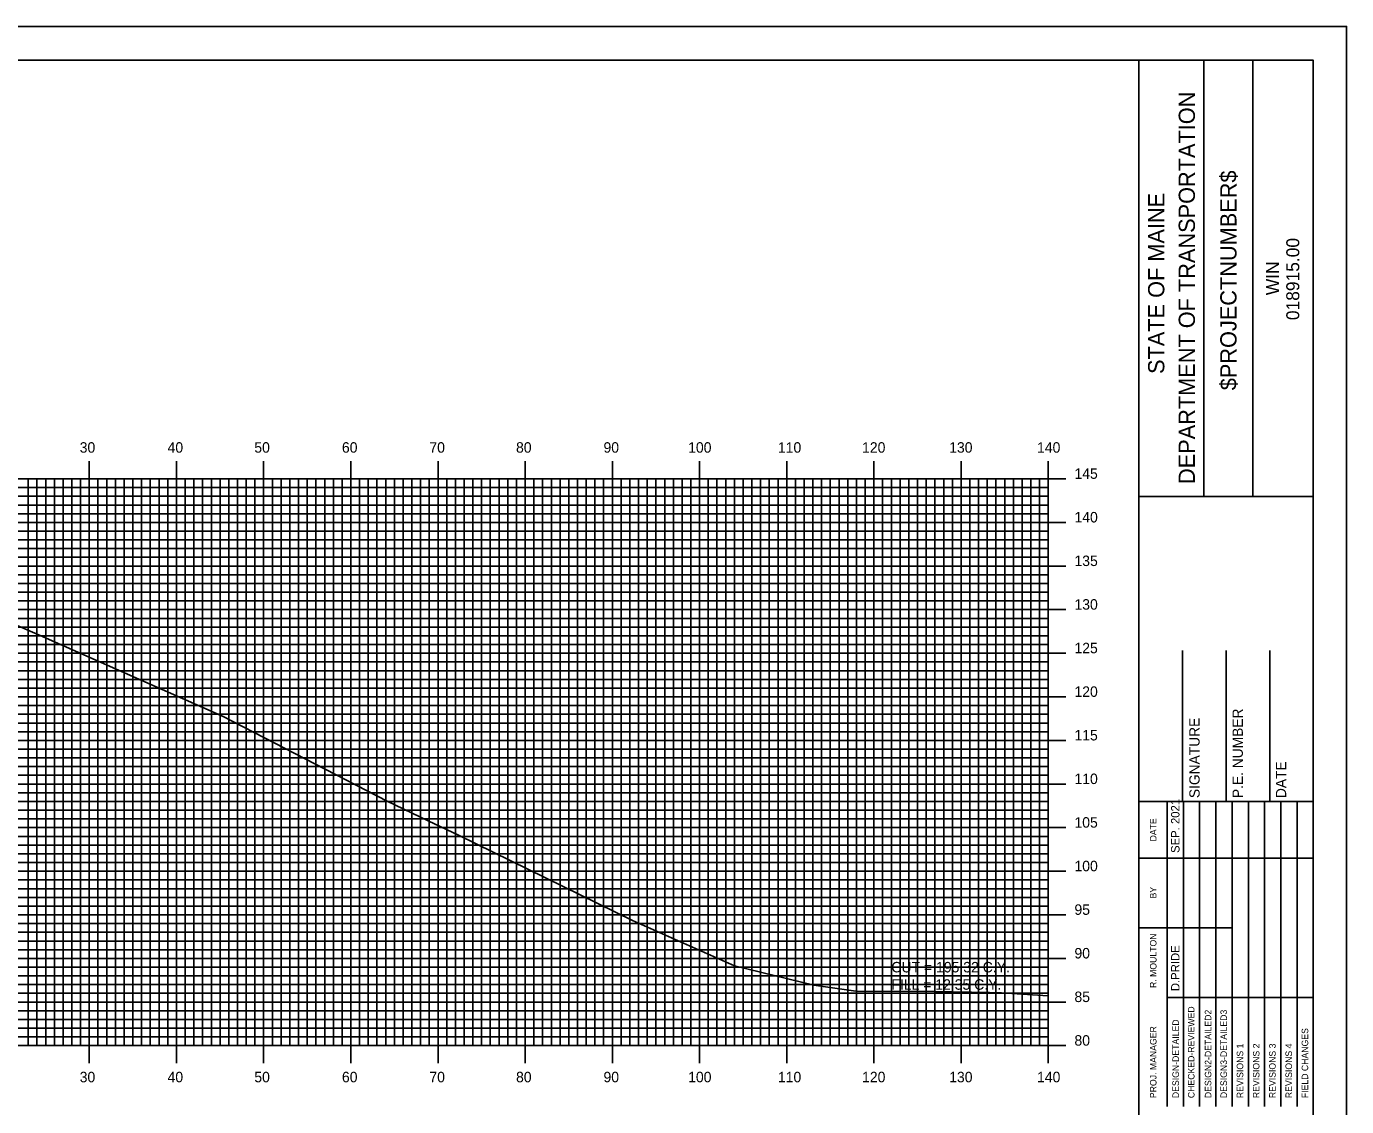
# Model space of a CAD drawing. Extents: x 859471 to 859814, y 364765 to 364985.
# Drawn here: x 859659.7 to 859811.1, y 364861.3 to 364985.2 of the extents above; entities that cross this region are included whole.
import ezdxf

# ---------------------------------------------------------------- set-up
doc = ezdxf.new("R2010")
doc.units = 0
for name, color, linetype in [('BORDER', 7, 'Continuous'), ('D_Text_Standard', 7, 'Continuous'), ('H_V ANNOTATION', 7, 'Continuous'), ('MAJOR', 7, 'Continuous'), ('MINOR', 7, 'Continuous'), ('PLOT BOUNDARY', 7, 'Continuous'), ('S_Roadway_Centerline', 7, 'Continuous')]:
    doc.layers.add(name, color=color, linetype=linetype)

msp = doc.modelspace()

# ---------------------------------------------------------------- linework, layer by layer
at = {"layer": 'BORDER'}
for p, q in [((859787.27, 364771.3), (859787.27, 364981.3)), ((859794.73, 364931.3), (859794.73, 364981.3)), ((859800.32, 364931.3), (859800.32, 364981.3)), ((859787.27, 364931.29), (859807.27, 364931.29)), ((859792.27, 364896.31), (859792.27, 364913.6)), ((859797.27, 364896.31), (859797.27, 364913.6)), ((859802.27, 364896.31), (859802.27, 364913.6)), ((859787.27, 364896.31), (859807.27, 364896.31))]:
    msp.add_line(p, q, dxfattribs=at)
msp.add_lwpolyline([(859487.27, 364771.3), (859807.27, 364771.3), (859807.27, 364981.3), (859487.27, 364981.3)], close=True, dxfattribs=at)
for points in [[(859790.5, 364889.81), (859790.5, 364896.31)], [(859792.37, 364861.31), (859792.37, 364896.31)], [(859794.23, 364896.31), (859794.23, 364861.31)], [(859796.09, 364861.31), (859796.09, 364896.31)], [(859797.96, 364861.31), (859797.96, 364896.31)], [(859799.82, 364861.31), (859799.82, 364896.31)], [(859801.68, 364861.31), (859801.68, 364896.31)], [(859803.55, 364861.31), (859803.55, 364896.31)], [(859805.41, 364861.31), (859805.41, 364896.31)], [(859790.5, 364861.31), (859790.5, 364894.9)], [(859787.27, 364889.81), (859807.27, 364889.81)], [(859787.27, 364881.81), (859790.5, 364881.81)], [(859790.5, 364881.81), (859797.96, 364881.81)], [(859790.5, 364873.81), (859807.27, 364873.81)]]:
    msp.add_lwpolyline(points, dxfattribs=at)
at = {"layer": 'MAJOR'}
for p, q in [((859666.87, 364935.31), (859666.87, 364933.3)), ((859676.87, 364935.31), (859676.87, 364933.3)), ((859686.87, 364935.31), (859686.87, 364933.3)), ((859696.87, 364935.31), (859696.87, 364933.3)), ((859706.87, 364935.31), (859706.87, 364933.3)), ((859716.87, 364935.31), (859716.87, 364933.3)), ((859726.87, 364935.31), (859726.87, 364933.3)), ((859736.87, 364935.31), (859736.87, 364933.3)), ((859746.87, 364935.31), (859746.87, 364933.3)), ((859756.87, 364935.31), (859756.87, 364933.3)), ((859766.87, 364935.31), (859766.87, 364933.3)), ((859776.87, 364935.31), (859776.87, 364933.3)), ((859496.87, 364933.3), (859776.87, 364933.3)), ((859496.87, 364933.3), (859776.87, 364933.3)), ((859666.87, 364868.3), (859666.87, 364933.3)), ((859676.87, 364868.3), (859676.87, 364933.3)), ((859686.87, 364868.3), (859686.87, 364933.3)), ((859696.87, 364868.3), (859696.87, 364933.3)), ((859706.87, 364868.3), (859706.87, 364933.3)), ((859716.87, 364868.3), (859716.87, 364933.3)), ((859726.87, 364868.3), (859726.87, 364933.3)), ((859736.87, 364868.3), (859736.87, 364933.3)), ((859746.87, 364868.3), (859746.87, 364933.3)), ((859756.87, 364868.3), (859756.87, 364933.3)), ((859766.87, 364868.3), (859766.87, 364933.3)), ((859778.88, 364933.3), (859774.87, 364933.3)), ((859776.87, 364868.3), (859776.87, 364933.3)), ((859776.87, 364868.3), (859776.87, 364933.3)), ((859496.87, 364928.3), (859776.87, 364928.3)), ((859778.88, 364928.3), (859774.87, 364928.3)), ((859496.87, 364923.3), (859776.87, 364923.3)), ((859778.88, 364923.3), (859774.87, 364923.3)), ((859496.87, 364918.3), (859776.87, 364918.3)), ((859778.88, 364918.3), (859774.87, 364918.3)), ((859496.87, 364913.3), (859776.87, 364913.3)), ((859778.88, 364913.3), (859774.87, 364913.3)), ((859496.87, 364908.3), (859776.87, 364908.3)), ((859778.88, 364908.3), (859774.87, 364908.3)), ((859496.87, 364903.3), (859776.87, 364903.3)), ((859778.88, 364903.3), (859774.87, 364903.3)), ((859496.87, 364898.3), (859776.87, 364898.3)), ((859778.88, 364898.3), (859774.87, 364898.3)), ((859496.87, 364893.3), (859776.87, 364893.3)), ((859778.88, 364893.3), (859774.87, 364893.3)), ((859496.87, 364888.3), (859776.87, 364888.3)), ((859778.88, 364888.3), (859774.87, 364888.3)), ((859496.87, 364883.3), (859776.87, 364883.3)), ((859778.88, 364883.3), (859774.87, 364883.3)), ((859496.87, 364878.3), (859776.87, 364878.3)), ((859778.88, 364878.3), (859774.87, 364878.3)), ((859496.87, 364873.3), (859776.87, 364873.3)), ((859778.88, 364873.3), (859774.87, 364873.3)), ((859496.87, 364868.3), (859776.87, 364868.3)), ((859496.87, 364868.3), (859776.87, 364868.3)), ((859666.87, 364866.3), (859666.87, 364868.3)), ((859676.87, 364866.3), (859676.87, 364868.3)), ((859686.87, 364866.3), (859686.87, 364868.3)), ((859696.87, 364866.3), (859696.87, 364868.3)), ((859706.87, 364866.3), (859706.87, 364868.3)), ((859716.87, 364866.3), (859716.87, 364868.3)), ((859726.87, 364866.3), (859726.87, 364868.3)), ((859736.87, 364866.3), (859736.87, 364868.3)), ((859746.87, 364866.3), (859746.87, 364868.3)), ((859756.87, 364866.3), (859756.87, 364868.3)), ((859766.87, 364866.3), (859766.87, 364868.3)), ((859778.88, 364868.3), (859774.87, 364868.3)), ((859776.87, 364866.3), (859776.87, 364868.3))]:
    msp.add_line(p, q, dxfattribs=at)
at = {"layer": 'MINOR'}
for p, q in [((859659.87, 364868.3), (859659.87, 364933.3)), ((859660.87, 364868.3), (859660.87, 364933.3)), ((859661.87, 364868.3), (859661.87, 364933.3)), ((859662.87, 364868.3), (859662.87, 364933.3)), ((859663.87, 364868.3), (859663.87, 364933.3)), ((859664.87, 364868.3), (859664.87, 364933.3)), ((859665.87, 364868.3), (859665.87, 364933.3)), ((859667.87, 364868.3), (859667.87, 364933.3)), ((859668.87, 364868.3), (859668.87, 364933.3)), ((859669.87, 364868.3), (859669.87, 364933.3)), ((859670.87, 364868.3), (859670.87, 364933.3)), ((859671.87, 364868.3), (859671.87, 364933.3)), ((859672.87, 364868.3), (859672.87, 364933.3)), ((859673.87, 364868.3), (859673.87, 364933.3)), ((859674.87, 364868.3), (859674.87, 364933.3)), ((859675.87, 364868.3), (859675.87, 364933.3)), ((859677.87, 364868.3), (859677.87, 364933.3)), ((859678.87, 364868.3), (859678.87, 364933.3)), ((859679.87, 364868.3), (859679.87, 364933.3)), ((859680.87, 364868.3), (859680.87, 364933.3)), ((859681.87, 364868.3), (859681.87, 364933.3)), ((859682.87, 364868.3), (859682.87, 364933.3)), ((859683.87, 364868.3), (859683.87, 364933.3)), ((859684.87, 364868.3), (859684.87, 364933.3)), ((859685.87, 364868.3), (859685.87, 364933.3)), ((859687.87, 364868.3), (859687.87, 364933.3)), ((859688.87, 364868.3), (859688.87, 364933.3)), ((859689.87, 364868.3), (859689.87, 364933.3)), ((859690.87, 364868.3), (859690.87, 364933.3)), ((859691.87, 364868.3), (859691.87, 364933.3)), ((859692.87, 364868.3), (859692.87, 364933.3)), ((859693.87, 364868.3), (859693.87, 364933.3)), ((859694.87, 364868.3), (859694.87, 364933.3)), ((859695.87, 364868.3), (859695.87, 364933.3)), ((859697.87, 364868.3), (859697.87, 364933.3)), ((859698.87, 364868.3), (859698.87, 364933.3)), ((859699.87, 364868.3), (859699.87, 364933.3)), ((859700.87, 364868.3), (859700.87, 364933.3)), ((859701.87, 364868.3), (859701.87, 364933.3)), ((859702.87, 364868.3), (859702.87, 364933.3)), ((859703.87, 364868.3), (859703.87, 364933.3)), ((859704.87, 364868.3), (859704.87, 364933.3)), ((859705.87, 364868.3), (859705.87, 364933.3)), ((859707.87, 364868.3), (859707.87, 364933.3)), ((859708.87, 364868.3), (859708.87, 364933.3)), ((859709.87, 364868.3), (859709.87, 364933.3)), ((859710.87, 364868.3), (859710.87, 364933.3)), ((859711.87, 364868.3), (859711.87, 364933.3)), ((859712.87, 364868.3), (859712.87, 364933.3)), ((859713.87, 364868.3), (859713.87, 364933.3)), ((859714.87, 364868.3), (859714.87, 364933.3)), ((859715.87, 364868.3), (859715.87, 364933.3)), ((859717.87, 364868.3), (859717.87, 364933.3)), ((859718.87, 364868.3), (859718.87, 364933.3)), ((859719.87, 364868.3), (859719.87, 364933.3)), ((859720.87, 364868.3), (859720.87, 364933.3)), ((859721.87, 364868.3), (859721.87, 364933.3)), ((859722.87, 364868.3), (859722.87, 364933.3)), ((859723.87, 364868.3), (859723.87, 364933.3)), ((859724.87, 364868.3), (859724.87, 364933.3)), ((859725.87, 364868.3), (859725.87, 364933.3)), ((859727.87, 364868.3), (859727.87, 364933.3)), ((859728.87, 364868.3), (859728.87, 364933.3)), ((859729.87, 364868.3), (859729.87, 364933.3)), ((859730.87, 364868.3), (859730.87, 364933.3)), ((859731.87, 364868.3), (859731.87, 364933.3)), ((859732.87, 364868.3), (859732.87, 364933.3)), ((859733.87, 364868.3), (859733.87, 364933.3)), ((859734.87, 364868.3), (859734.87, 364933.3)), ((859735.87, 364868.3), (859735.87, 364933.3)), ((859737.87, 364868.3), (859737.87, 364933.3)), ((859738.87, 364868.3), (859738.87, 364933.3)), ((859739.87, 364868.3), (859739.87, 364933.3)), ((859740.87, 364868.3), (859740.87, 364933.3)), ((859741.87, 364868.3), (859741.87, 364933.3)), ((859742.87, 364868.3), (859742.87, 364933.3)), ((859743.87, 364868.3), (859743.87, 364933.3)), ((859744.87, 364868.3), (859744.87, 364933.3)), ((859745.87, 364868.3), (859745.87, 364933.3)), ((859747.87, 364868.3), (859747.87, 364933.3)), ((859748.87, 364868.3), (859748.87, 364933.3)), ((859749.87, 364868.3), (859749.87, 364933.3)), ((859750.87, 364868.3), (859750.87, 364933.3)), ((859751.87, 364868.3), (859751.87, 364933.3)), ((859752.87, 364868.3), (859752.87, 364933.3)), ((859753.87, 364868.3), (859753.87, 364933.3)), ((859754.87, 364868.3), (859754.87, 364933.3)), ((859755.87, 364868.3), (859755.87, 364933.3)), ((859757.87, 364868.3), (859757.87, 364933.3)), ((859758.87, 364868.3), (859758.87, 364933.3)), ((859759.87, 364868.3), (859759.87, 364933.3)), ((859760.87, 364868.3), (859760.87, 364933.3)), ((859761.87, 364868.3), (859761.87, 364933.3)), ((859762.87, 364868.3), (859762.87, 364933.3)), ((859763.87, 364868.3), (859763.87, 364933.3)), ((859764.87, 364868.3), (859764.87, 364933.3)), ((859765.87, 364868.3), (859765.87, 364933.3)), ((859767.87, 364868.3), (859767.87, 364933.3)), ((859768.87, 364868.3), (859768.87, 364933.3)), ((859769.87, 364868.3), (859769.87, 364933.3)), ((859770.87, 364868.3), (859770.87, 364933.3)), ((859771.87, 364868.3), (859771.87, 364933.3)), ((859772.87, 364868.3), (859772.87, 364933.3)), ((859773.87, 364868.3), (859773.87, 364933.3)), ((859774.87, 364868.3), (859774.87, 364933.3)), ((859775.87, 364868.3), (859775.87, 364933.3)), ((859496.87, 364932.3), (859776.87, 364932.3)), ((859776.87, 364932.3), (859774.87, 364932.3)), ((859496.87, 364931.3), (859776.87, 364931.3)), ((859496.87, 364930.3), (859776.87, 364930.3)), ((859776.87, 364931.3), (859774.87, 364931.3)), ((859776.87, 364930.3), (859774.87, 364930.3)), ((859496.87, 364929.3), (859776.87, 364929.3)), ((859776.87, 364929.3), (859774.87, 364929.3)), ((859496.87, 364927.3), (859776.87, 364927.3)), ((859776.87, 364927.3), (859774.87, 364927.3)), ((859496.87, 364926.3), (859776.87, 364926.3)), ((859776.87, 364926.3), (859774.87, 364926.3)), ((859496.87, 364925.3), (859776.87, 364925.3)), ((859496.87, 364924.3), (859776.87, 364924.3)), ((859776.87, 364925.3), (859774.87, 364925.3)), ((859776.87, 364924.3), (859774.87, 364924.3)), ((859496.87, 364922.3), (859776.87, 364922.3)), ((859776.87, 364922.3), (859774.87, 364922.3)), ((859496.87, 364921.3), (859776.87, 364921.3)), ((859776.87, 364921.3), (859774.87, 364921.3)), ((859496.87, 364920.3), (859776.87, 364920.3)), ((859496.87, 364919.3), (859776.87, 364919.3)), ((859776.87, 364920.3), (859774.87, 364920.3)), ((859776.87, 364919.3), (859774.87, 364919.3)), ((859496.87, 364917.3), (859776.87, 364917.3)), ((859496.87, 364916.3), (859776.87, 364916.3)), ((859776.87, 364917.3), (859774.87, 364917.3)), ((859776.87, 364916.3), (859774.87, 364916.3)), ((859496.87, 364915.3), (859776.87, 364915.3)), ((859776.87, 364915.3), (859774.87, 364915.3)), ((859496.87, 364914.3), (859776.87, 364914.3)), ((859776.87, 364914.3), (859774.87, 364914.3)), ((859496.87, 364912.3), (859776.87, 364912.3)), ((859776.87, 364912.3), (859774.87, 364912.3)), ((859496.87, 364911.3), (859776.87, 364911.3)), ((859496.87, 364910.3), (859776.87, 364910.3)), ((859776.87, 364911.3), (859774.87, 364911.3)), ((859776.87, 364910.3), (859774.87, 364910.3)), ((859496.87, 364909.3), (859776.87, 364909.3)), ((859776.87, 364909.3), (859774.87, 364909.3)), ((859496.87, 364907.3), (859776.87, 364907.3)), ((859776.87, 364907.3), (859774.87, 364907.3)), ((859496.87, 364906.3), (859776.87, 364906.3)), ((859776.87, 364906.3), (859774.87, 364906.3)), ((859496.87, 364905.3), (859776.87, 364905.3)), ((859496.87, 364904.3), (859776.87, 364904.3)), ((859776.87, 364905.3), (859774.87, 364905.3)), ((859776.87, 364904.3), (859774.87, 364904.3)), ((859496.87, 364902.3), (859776.87, 364902.3)), ((859496.87, 364901.3), (859776.87, 364901.3)), ((859776.87, 364902.3), (859774.87, 364902.3)), ((859776.87, 364901.3), (859774.87, 364901.3)), ((859496.87, 364900.3), (859776.87, 364900.3)), ((859776.87, 364900.3), (859774.87, 364900.3)), ((859496.87, 364899.3), (859776.87, 364899.3)), ((859776.87, 364899.3), (859774.87, 364899.3)), ((859496.87, 364897.3), (859776.87, 364897.3)), ((859776.87, 364897.3), (859774.87, 364897.3)), ((859496.87, 364896.3), (859776.87, 364896.3)), ((859496.87, 364895.3), (859776.87, 364895.3)), ((859776.87, 364896.3), (859774.87, 364896.3)), ((859776.87, 364895.3), (859774.87, 364895.3)), ((859496.87, 364894.3), (859776.87, 364894.3)), ((859776.87, 364894.3), (859774.87, 364894.3)), ((859496.87, 364892.3), (859776.87, 364892.3)), ((859776.87, 364892.3), (859774.87, 364892.3)), ((859496.87, 364891.3), (859776.87, 364891.3)), ((859776.87, 364891.3), (859774.87, 364891.3)), ((859496.87, 364890.3), (859776.87, 364890.3)), ((859496.87, 364889.3), (859776.87, 364889.3)), ((859776.87, 364890.3), (859774.87, 364890.3)), ((859776.87, 364889.3), (859774.87, 364889.3)), ((859496.87, 364887.3), (859776.87, 364887.3)), ((859496.87, 364886.3), (859776.87, 364886.3)), ((859776.87, 364887.3), (859774.87, 364887.3)), ((859776.87, 364886.3), (859774.87, 364886.3)), ((859496.87, 364885.3), (859776.87, 364885.3)), ((859776.87, 364885.3), (859774.87, 364885.3)), ((859496.87, 364884.3), (859776.87, 364884.3)), ((859776.87, 364884.3), (859774.87, 364884.3)), ((859496.87, 364882.3), (859776.87, 364882.3)), ((859776.87, 364882.3), (859774.87, 364882.3)), ((859496.87, 364881.3), (859776.87, 364881.3)), ((859496.87, 364880.3), (859776.87, 364880.3)), ((859776.87, 364881.3), (859774.87, 364881.3)), ((859776.87, 364880.3), (859774.87, 364880.3)), ((859496.87, 364879.3), (859776.87, 364879.3)), ((859776.87, 364879.3), (859774.87, 364879.3)), ((859496.87, 364877.3), (859776.87, 364877.3)), ((859776.87, 364877.3), (859774.87, 364877.3)), ((859496.87, 364876.3), (859776.87, 364876.3)), ((859776.87, 364876.3), (859774.87, 364876.3)), ((859496.87, 364875.3), (859776.87, 364875.3)), ((859496.87, 364874.3), (859776.87, 364874.3)), ((859776.87, 364875.3), (859774.87, 364875.3)), ((859776.87, 364874.3), (859774.87, 364874.3)), ((859496.87, 364872.3), (859776.87, 364872.3)), ((859496.87, 364871.3), (859776.87, 364871.3)), ((859776.87, 364872.3), (859774.87, 364872.3)), ((859776.87, 364871.3), (859774.87, 364871.3)), ((859496.87, 364870.3), (859776.87, 364870.3)), ((859496.87, 364869.3), (859776.87, 364869.3)), ((859776.87, 364870.3), (859774.87, 364870.3)), ((859776.87, 364869.3), (859774.87, 364869.3))]:
    msp.add_line(p, q, dxfattribs=at)
at = {"layer": 'PLOT BOUNDARY'}
msp.add_lwpolyline([(859471.09, 364765.18), (859811.09, 364765.18), (859811.09, 364985.18), (859471.09, 364985.18)], close=True, dxfattribs=at)
at = {"layer": 'S_Roadway_Centerline'}
msp.add_lwpolyline([(859644.46, 364922.65), (859661.25, 364915.33), (859682.24, 364906.05), (859701.05, 364896.35), (859705.74, 364894.08), (859709.21, 364892.43), (859717.16, 364888.54), (859729.17, 364882.64), (859740.88, 364877.47), (859749.99, 364875.24), (859754.78, 364874.56), (859763.91, 364874.51), (859770.14, 364874.4), (859771.49, 364874.36), (859776.87, 364874)], dxfattribs=at)

# ---------------------------------------------------------------- texts
at = {"layer": 'BORDER'}
for s, height, p in [('DEPARTMENT OF TRANSPORTATION', 1.8635, (859793.69, 364932.71)), ('$PROJECTNUMBER$', 1.8635, (859798.46, 364943.46)), ('STATE OF MAINE', 1.8635, (859790.18, 364945.33)), ('018915.00', 1.491, (859805.66, 364951.5)), ('WIN', 1.491, (859803.35, 364954.36)), ('SIGNATURE', 1.181, (859794.23, 364896.69)), ('P.E. NUMBER', 1.1811, (859799.19, 364896.69)), ('DATE', 1.181, (859804.16, 364896.69)), ('SEP. 2021', 0.969, (859791.92, 364890.4)), ('DATE', 0.743, (859789.28, 364891.72)), ('BY', 0.743, (859789.28, 364885.18)), ('R. MOULTON', 0.745, (859789.28, 364874.91)), ('D.PRIDE', 0.969, (859791.92, 364874.55)), ('CHECKED-REVIEWED', 0.7455, (859793.64, 364862.28)), ('DESIGN2-DETAILED2', 0.7455, (859795.57, 364862.28)), ('DESIGN3-DETAILED3', 0.7455, (859797.36, 364862.28)), ('DESIGN-DETAILED', 0.7455, (859791.85, 364862.28)), ('PROJ. MANAGER', 0.7455, (859789.28, 364862.28)), ('FIELD CHANGES', 0.7455, (859806.68, 364862.28)), ('REVISIONS 1', 0.7455, (859799.23, 364862.28)), ('REVISIONS 2', 0.7455, (859801.09, 364862.28)), ('REVISIONS 3', 0.7455, (859802.95, 364862.28)), ('REVISIONS 4', 0.7455, (859804.82, 364862.28))]:
    msp.add_text(s, height=height, rotation=90, dxfattribs=at).set_placement(p)
at = {"layer": 'D_Text_Standard'}
for s, p in [('CUT = 195.32 C.Y.', (859758.87, 364876.7)), ('FILL = 12.35 C.Y.', (859758.87, 364874.71))]:
    msp.add_text(s, height=1.2, dxfattribs=at).set_placement(p)
at = {"layer": 'H_V ANNOTATION'}
for s, p in [('30', (859665.77, 364936.3)), ('40', (859675.85, 364936.3)), ('50', (859685.8, 364936.3)), ('60', (859695.85, 364936.3)), ('70', (859705.88, 364936.3)), ('80', (859715.82, 364936.3)), ('90', (859725.85, 364936.3)), ('100', (859735.56, 364936.3)), ('110', (859745.86, 364936.3)), ('120', (859755.51, 364936.3)), ('130', (859765.5, 364936.3)), ('140', (859775.58, 364936.3)), ('145', (859779.87, 364933.3)), ('140', (859779.87, 364928.3)), ('135', (859779.87, 364923.3)), ('130', (859779.87, 364918.3)), ('125', (859779.87, 364913.3)), ('120', (859779.87, 364908.3)), ('115', (859779.87, 364903.3)), ('110', (859779.87, 364898.3)), ('105', (859779.87, 364893.3)), ('100', (859779.87, 364888.3)), ('95', (859779.87, 364883.3)), ('90', (859779.87, 364878.3)), ('85', (859779.87, 364873.3)), ('80', (859779.87, 364868.3)), ('30', (859665.77, 364864.1)), ('40', (859675.85, 364864.1)), ('50', (859685.8, 364864.1)), ('60', (859695.85, 364864.1)), ('70', (859705.88, 364864.1)), ('80', (859715.82, 364864.1)), ('90', (859725.85, 364864.1)), ('100', (859735.56, 364864.1)), ('110', (859745.86, 364864.1)), ('120', (859755.51, 364864.1)), ('130', (859765.5, 364864.1)), ('140', (859775.58, 364864.1))]:
    msp.add_text(s, height=1.2, dxfattribs=at).set_placement(p)

doc.saveas('drawing.dxf')
